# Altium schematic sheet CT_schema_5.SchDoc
size 188 x 165 mm
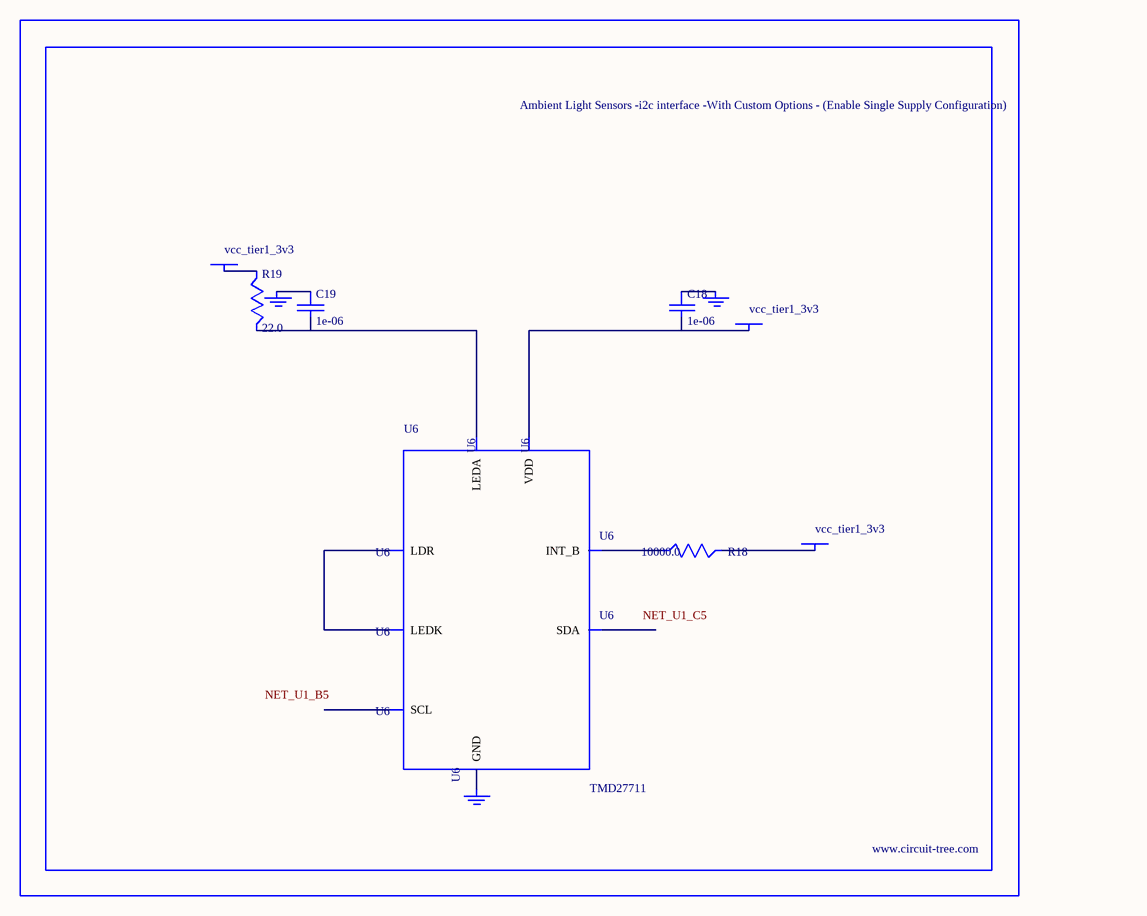
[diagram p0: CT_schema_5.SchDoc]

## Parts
BORDER4  (no value)
C18  1e-06  [C0603]
C19  1e-06  [C0603]
GND_INSTANCE_4_0  (no value)
GND_INSTANCE_4_1  (no value)
GND_INSTANCE_4_2  (no value)
POWER_INSTANCE_4_0  vcc_tier1_3v3
POWER_INSTANCE_4_1  vcc_tier1_3v3
POWER_INSTANCE_4_2  vcc_tier1_3v3
R18  10000.0  [R0603]
R19  22.0  [R0603]
U6  TMD27711  [SMD-8]

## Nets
NetC18_1: C18.1 GND_INSTANCE_4_0.0(GND)
NetC18_2: C18.2 POWER_INSTANCE_4_0.0(PWR) U6.1(VDD)
NetC19_1: C19.1 GND_INSTANCE_4_1.0(GND)
NetC19_2: C19.2 R19.2 U6.4(LEDA)
NetGND_INSTANCE_4_2_0: GND_INSTANCE_4_2.0(GND) U6.3(GND)
NetPOWER_INSTANCE_4_1_0: POWER_INSTANCE_4_1.0(PWR) R19.1
NetPOWER_INSTANCE_4_2_0: POWER_INSTANCE_4_2.0(PWR) R18.2
NetR18_1: R18.1 U6.7(INT_B)
NetU6_5: U6.5(LEDK) U6.6(LDR)

Not connected (* = marked no-connect by the designer): U6 2(SCL) 8(SDA)

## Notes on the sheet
- Labels drawn without touching a wire or pin: NET_U1_B5, NET_U1_C5

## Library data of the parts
BORDER4 = BORDER_PAGE4
C18 C19 = C0603C105K3RACTU
GND_INSTANCE_4_0-GND_INSTANCE_4_2 = GND
POWER_INSTANCE_4_0-POWER_INSTANCE_4_2 = PWR
R18 = RC0603JR-0710KL
R19 = RC0603JR-0722RL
